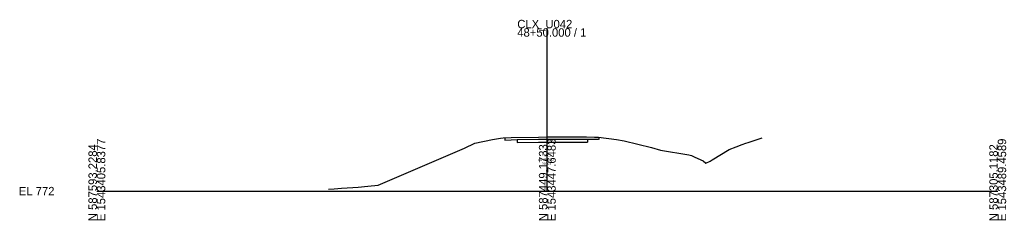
# Model space of a CAD drawing. Extents: x -26 to 1603, y -10 to 5557.
# Drawn here: x -25.7 to 302.8, y 5490.3 to 5557 of the extents above; entities that cross this region are included whole.
import ezdxf

# ---------------------------------------------------------------- set-up
doc = ezdxf.new("R2010")
doc.units = 0
for name, color, linetype in [('GK_Cells', 7, 'Continuous'), ('XS_P_Annotation', 7, 'Continuous'), ('XS_X_Ground_Line', 7, 'Continuous'), ('XS_X_Pavt', 7, 'Continuous')]:
    doc.layers.add(name, color=color, linetype=linetype)

msp = doc.modelspace()

# ---------------------------------------------------------------- linework, layer by layer
at = {"layer": 'GK_Cells'}
for p, q in [((150, 5500), (150, 5554.19)), ((0, 5500), (150, 5500)), ((150, 5500), (300, 5500))]:
    msp.add_line(p, q, dxfattribs=at)
at = {"layer": 'XS_X_Ground_Line'}
msp.add_lwpolyline([(77.14, 5500.63), (79.01, 5500.76), (81.5, 5500.93), (85.18, 5501.17), (87, 5501.3), (90.2, 5501.6), (93.67, 5501.93), (122.39, 5514.25), (125.81, 5515.98), (131.72, 5517.14), (134.42, 5517.67), (135.31, 5517.72), (138.01, 5517.87), (147.06, 5517.99), (150, 5518.03), (151.17, 5518.04), (156.34, 5518.05), (163.1, 5518.06), (165.67, 5518.01), (167, 5517.99), (173.03, 5517.14), (175.61, 5516.77), (184.65, 5514.47), (187.74, 5513.68), (197.09, 5512.06), (198.06, 5511.89), (199.17, 5511.35), (201.87, 5510.05), (202.77, 5509.26), (204.19, 5509.94), (204.89, 5510.38), (210.58, 5513.9), (212.91, 5514.75), (214.92, 5515.48), (216.13, 5515.91), (216.93, 5516.21), (217.5, 5516.41), (221.6, 5517.69)], dxfattribs=at)
at = {"layer": 'XS_X_Pavt'}
for p, q in [((135.8, 5517.75), (135.8, 5517)), ((135.8, 5517), (138.01, 5517.12)), ((138.01, 5517.12), (139.99, 5517.15)), ((139.99, 5517.15), (147.06, 5517.24)), ((139.99, 5517.15), (139.99, 5516.15)), ((139.99, 5516.15), (147.06, 5516.24)), ((147.06, 5517.24), (150, 5517.28)), ((147.06, 5516.24), (150, 5516.28)), ((150, 5517.28), (151.17, 5517.29)), ((150, 5516.28), (151.17, 5516.29)), ((151.17, 5517.29), (156.34, 5517.3)), ((151.17, 5516.29), (156.34, 5516.3)), ((156.34, 5517.3), (163.1, 5517.31)), ((156.34, 5516.3), (163.1, 5516.31)), ((163.1, 5517.31), (163.43, 5517.31)), ((163.1, 5516.31), (163.43, 5516.31)), ((163.43, 5517.31), (165.67, 5517.26)), ((163.43, 5517.31), (163.43, 5516.31)), ((165.67, 5517.26), (167, 5517.24)), ((167, 5517.24), (167.2, 5517.21)), ((167.2, 5517.96), (167.2, 5517.21))]:
    msp.add_line(p, q, dxfattribs=at)

# ---------------------------------------------------------------- texts
at = {"layer": 'GK_Cells'}
for s, p in [('CLX_U042', (140, 5554.19)), ('48+50.000 / 1', (140, 5551.39)), ('EL 772', (-26, 5498.6))]:
    msp.add_text(s, height=2.8, dxfattribs=at).set_placement(p)
for s, p in [('E 1543405.8377', (2.8, 5490)), ('E 1543447.6483', (152.8, 5490)), ('E 1543489.4589', (302.8, 5490)), ('N 587593.2284', (0, 5490)), ('N 587449.1733', (150, 5490)), ('N 587305.1182', (300, 5490))]:
    msp.add_text(s, height=2.8, rotation=90, dxfattribs=at).set_placement(p)
at = {"layer": 'XS_P_Annotation'}
for s, height, p in [('48+50.00', 0.9, (146.89, 5510.05)), ('790.03', 0.7, (148.23, 5511.55)), ('790.03', 0.7, (148.23, 5508.75))]:
    msp.add_text(s, height=height, dxfattribs=at).set_placement(p)

doc.saveas('drawing.dxf')
